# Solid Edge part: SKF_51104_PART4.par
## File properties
Title: SKF_51104_PART4
Author: psAdmin
Comments: Thrust ball bearings, single direction
Template: iso metric part.par
Last saved by: psAdmin
Revision: 1
Application: Solid Edge
Document Number: SKF_51104_PART4
Company: SKF
Density: 4,12018190605e+05 kg/m^3
Accuracy: 0,990
NB: SKF_51104_PART4
NT: Thrust ball bearings, single direction
NBSYN: SKF_$TC._PART4
LINA: SKF_51104_PART4
CATALOG: SKF
DESIGNATION: 51104
WASHER: No seat washer
DD: 20.0
D: 35.0
H: 10.00
LOAD1: 15.1
LOAD2: 29.0
LOAD3: 1.1
SPEED1: 7500
SPEED2: 10000
BEARING: 51104
SUPPLIER: SKF
ARTICLENO: SKF_51104_PART4
BOMINFO: SKF_51104_PART4
CREATOR: CADENAS GmbH
ID: skf:SKF_51104_PART4
CADENASIDSTR: DOCATTR{IDENT{"{$CADENAS_DATA/23d-libs/skf/bearings_units_and_housings/ball_bearings/thrust_ball_bearings/bd1_001_bdc_001.prj},207 {VTYP=3D},{NB=SKF_51104_PART4},{LINA=SKF_51104_PART4},{NN=BD1_001_BDC_001_PART4},{NOPRJ=TRUE},{DATE=08.09.2023 08:50:36},{GEOMDATE=04.09.2023 08:34:44},{VERSION=},{LINEID=46530},{WBVAR=WASHER},{WBNUMERIC=}  {NB=SKF_51104_PART4},{LINA=SKF_51104_PART4},{KT=DUMMY},{DESIGNATION=51104},{WASHER=},{DD=20.0},{D=35.0},{DX=},{DXX=MIN},{H=10.00},{H1=},{DD1=35.00},{D1=21.00},{D2=},{D3=},{C=},{R=},{SS=},{R12=0.3},{PITCH=27.500},{DW=5.556},{ALPHA=90},{DAMIN=29.00},{DAMAX=26.00},{RAMAX=0.30},{LOAD1=15.1},{LOAD2=29.0},{LOAD3=1.1},{SPEED1=7500},{SPEED2=10000},{A=0.0044},{Z=14},{II=1},{MASS=0.03700},{BEARING=51104},{WASHERVAR=},{POPULAR=Yes},{XHO=7.2224},{BHO=2.7776},{BSH=2.7776},{Y3=0},{H3=0},{B3=0},{WASHERALG='','No seat washer'},{WSPN=},{DESIGN=tbb1},{H1ALG=0},{SSALG=0},{RALG=0},{TC=51104},{DXA=35.000}"}}
Username: psAdmin
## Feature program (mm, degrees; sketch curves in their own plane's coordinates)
sketch for "unnamed RevolvedProtrusion 1" plane through (0, 0, 0) normal (0, 0, 1) x-axis (1, 0, 0)
revolve "unnamed RevolvedProtrusion 1" add finite 360 deg about sketch line (7.778, 13.75) -> (2.222, 13.75)
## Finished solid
Body 1: solid body, 1 face, 0 edges, 0 vertices.
  Faces by surface: sphere 1
Spherical faces by radius (mm): R2.778 x1
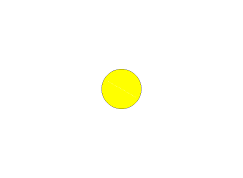
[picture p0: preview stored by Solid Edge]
